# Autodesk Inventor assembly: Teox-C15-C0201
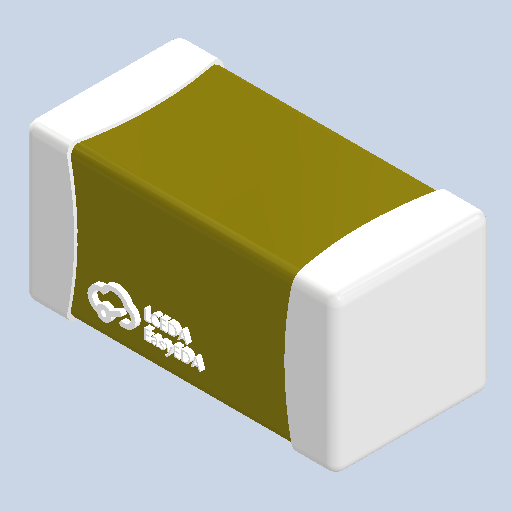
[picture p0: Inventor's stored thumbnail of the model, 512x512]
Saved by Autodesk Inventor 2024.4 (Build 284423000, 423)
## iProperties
Created: 2025-05
Part Number: Teox-C15-C0201
Document SubType Name: Assembly
Designer: AdminForWorker
Title: Teox-C15-C0201
Author: AdminForWorker
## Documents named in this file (2)
- c:\worker\convert-fusion-r02-cosv3\tmp\job-1\2\temp\files\be827049-a7f2-47ea-a815-8d9efd6bfce9\Teox-C15-C0201.iam
- c:\worker\convert-fusion-r02-cosv3\tmp\job-1\2\temp\files\be827049-a7f2-47ea-a815-8d9efd6bfce9\COMPOUND (3).ipt
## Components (1 placed, 1 different names)
1. COMPOUND (3):6
